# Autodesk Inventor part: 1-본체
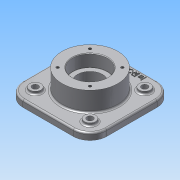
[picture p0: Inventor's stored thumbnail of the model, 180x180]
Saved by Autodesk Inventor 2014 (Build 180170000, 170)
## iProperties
Created: 2015-09
Part Number: 1-본체
Material: 알루미늄 6061
Document SubType Name: Modeling
Designer: study
Density: 2.71 g/cm^3
Appearance: 알루미늄 - 평지
Mass: 1464.68 g
Surface Area: 800.934 cm^2
Volume: 540.471 cm^3
Author: study
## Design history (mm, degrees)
sketch "스케치1"
  geometry: L1 (-75, 75)-(75, 75); L2 (75, 75)-(75, -75); L3 (75, -75)-(-75, -75); L4 (-75, -75)-(-75, 75); L5 (-75, 75)-(75, -75); L6 (75, 75)-(-75, -75); 1 further point
  constraints: 12 end point, 2 midpoint, 2 parallel, 1 horizontal, 1 perpendicular
  dimensions: "d0" = 150 distance of L1.start L1.end; "d1" = 150 distance of L1.end L2.end
extrude "돌출1" new body sketch "스케치1" distance "d2" = 12; taper "d3" = 0 deg
node "작업 평면1"
sketch "스케치2"
  geometry: C1 r 50 at (0, 0); 1 further point
  constraints: 1 centre point, 1 coincident
  dimensions: "d5" = 100 diameter of C1
extrude "돌출2" join sketch "스케치2" distance "d6" = 70; taper "d7" = 0 deg
hole "구멍1" diameter "d10" = 45; stored, may be unused: countersink angle "d14" = 90 deg, drill point angle "d16" = 118 deg; dims "d8" = 10, "d9" = 10, "d11" = 6, "d12" = 62, "d13" = 22, "d15" = 8
hole "구멍2" diameter "d19" = 45; stored, may be unused: countersink angle "d23" = 90 deg, drill point angle "d25" = 118 deg; dims "d17" = 10, "d18" = 10, "d20" = 6, "d21" = 62, "d22" = 22, "d24" = 8
sketch "스케치3"
  geometry: L1 (49, -49)-(-49, -49); L2 (-49, -49)-(-49, 49); L3 (-49, 49)-(49, 49); L4 (49, 49)-(49, -49); C1 r 50 at (0, 0) reference; C2 r 10 at (-49, 49); C3 r 10 at (49, 49); C4 r 10 at (-49, -49); C5 r 10 at (49, -49); 1 further point
  constraints: 8 end point, 5 coincident, 4 centre point, 3 equal radius, 1 horizontal, 9 other
  dimensions: "d26" = 98 distance of L2.end L3.end; "d27" = 20 diameter of C2
extrude "돌출3" join sketch "스케치3" distance "d28" = 5; taper "d29" = 0 deg
sketch "스케치4"
  geometry: C1 r 10 at (0, 0) reference; C2 r 10 at (98, 0) reference; C3 r 10 at (98, -98) reference; C4 r 10 at (0, -98) reference; 5 further points
  constraints: 4 coincident
hole "구멍3" sketch "스케치4" at (0, 0), (98, 0), (98, -98), (0, -98) diameter "d30" = 11; stored, may be unused: countersink angle "d34" = 90 deg, drill point angle "d36" = 118 deg; dims "d31" = 6, "d32" = 62, "d33" = 22, "d35" = 8
sketch "스케치5"
  geometry: L1 (28.991, -28.991)-(-28.991, -28.991); L2 (-28.991, -28.991)-(-28.991, 28.991); L3 (-28.991, 28.991)-(28.991, 28.991); L4 (28.991, 28.991)-(28.991, -28.991); C1 r 50 at (0, 0) reference; 5 further points
  constraints: 8 end point, 5 coincident, 1 horizontal, 9 other
  dimensions: "d37" = 82 distance of L1.end L3.end
hole "구멍4" sketch "스케치5" at (-28.991, 28.991), (28.991, 28.991), (28.991, -28.991), (-28.991, -28.991) diameter "d38" = 4.917; stored, may be unused: countersink angle "d42" = 90 deg, drill point angle "d44" = 118 deg; dims "d39" = 10, "d40" = 62, "d41" = 22, "d43" = 13
node "작업 평면2"
chamfer "모따기1" distance "d45" = 1; stored, may be unused: second distance "d46" = 2, angle "d47" = 45 deg
fillet "모깎기1" dims "d48" = 0.3, "d49" = 30
fillet "모깎기2" dims "d50" = 3
sketch "스케치6"
  geometry: C1 r 53 at (0, 0) reference; 1 further point
  constraints: 1 vertical alignment, 1 other
  dimensions: "d51" = 65 distance of point (0, 65) C1.centre
feature "엠보싱1" sketch "스케치6" dims "d0" = 150, "d1" = 150, "d52" = 1, "d53" = 0
node "솔리드1"
mirror "대칭1"
other parameters: "d4" = -23
